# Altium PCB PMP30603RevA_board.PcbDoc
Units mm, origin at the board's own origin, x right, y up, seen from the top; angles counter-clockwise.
Board outline 38.1 x 27.94 mm, 2 copper layers (Top Layer, Bottom Layer), stack 1.575 mm thick; 29 components, 12 nets, 77 pads, 41 vias.
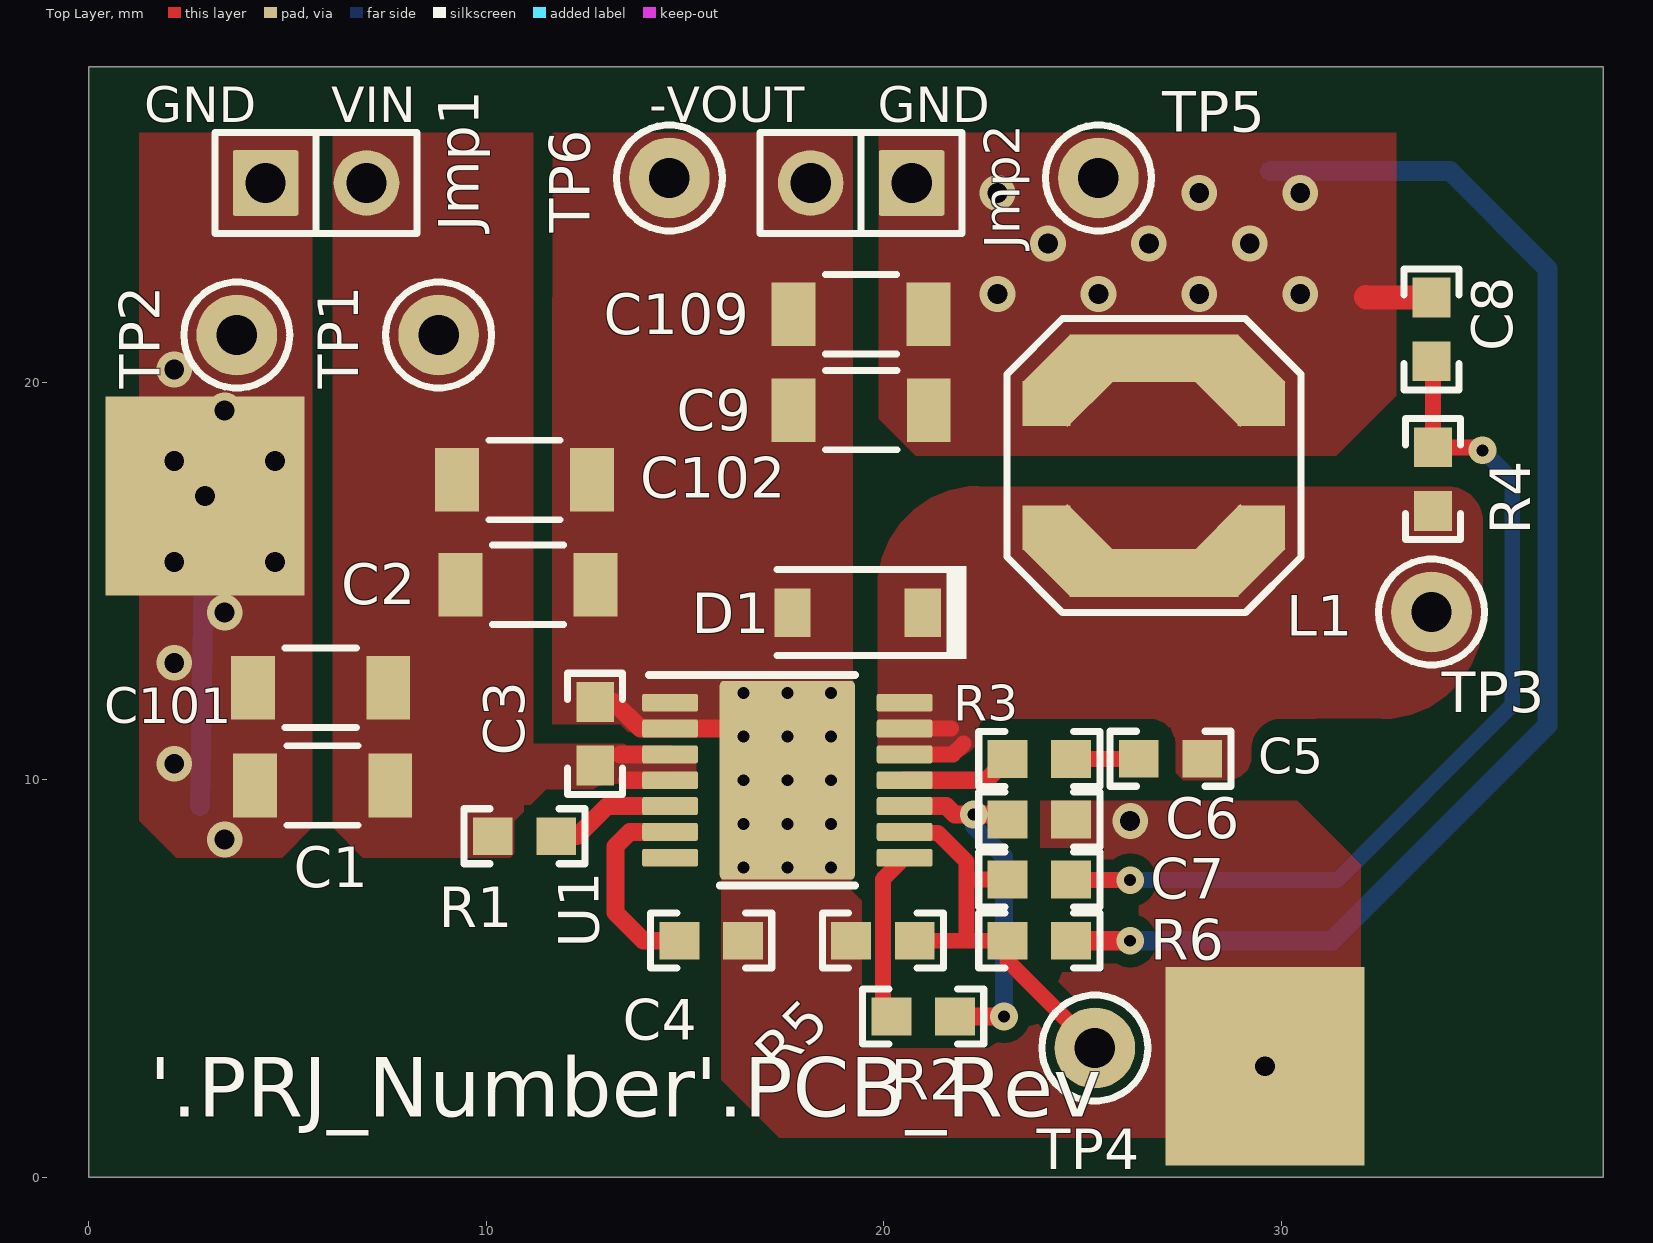
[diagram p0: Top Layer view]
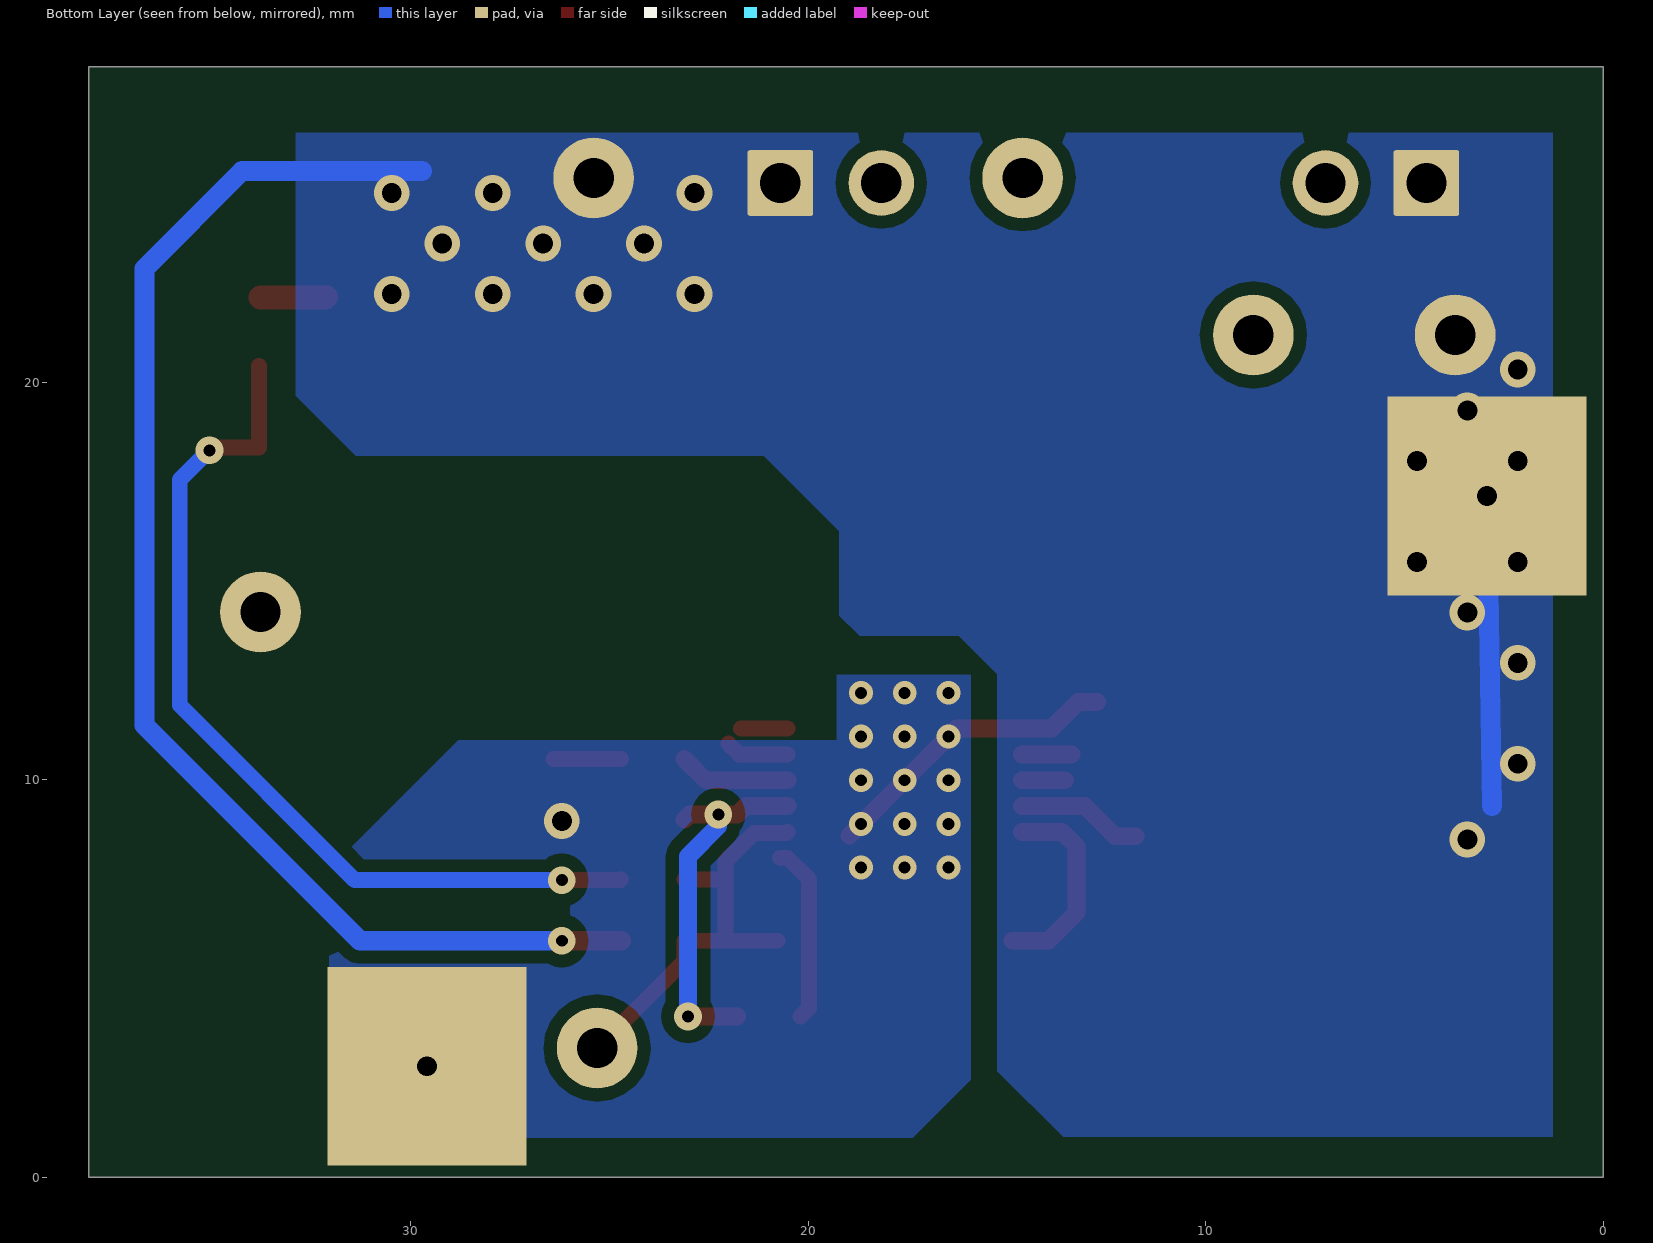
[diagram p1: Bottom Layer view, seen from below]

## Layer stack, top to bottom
Top Solder: solder mask 0.0102, Solder Resist, Dk 3.5
Top Layer: signal copper 0.0356
Dielectric1: core 1.5037, FR-4, Dk 4.8
Bottom Layer: signal copper 0.0356
Bottom Solder: solder mask 0.0102, Solder Resist, Dk 3.5

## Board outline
0,0 38.1,0 38.1,27.94 0,27.94

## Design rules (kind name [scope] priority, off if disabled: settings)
AcuteAngle [All] p1: minimum=4.50000000000000E+0001 checktracksonly=FALSE
AssemblyTestPointUsage [All] p1: valid=2
BoardOutlineClearance BoardOutlineClearance_MountingHoles [OnCopper and InComponentClass('Mounting Holes')] p1: gap=1 ignorepadtopadclearanceinfootprint=FALSE
BoardOutlineClearance BoardOutlineClearance_Poly [OnCopper and IsPoly] p2: gap=0.635 ignorepadtopadclearanceinfootprint=FALSE
BoardOutlineClearance [OnCopper and Not InComponentClass('Logo') and not InComponentClass('FiducialMark') and not InRegion(1000,500,4000,800) and not InPoly] p3: gap=1 ignorepadtopadclearanceinfootprint=FALSE
Clearance Clearance_Keepouts [((IsTrack Or IsArc) And Not InPoly) And IsFree and IsKeepOut vs ((IsTrack Or IsArc) And Not InPoly) And IsFree and IsKeepOut] p1: gap=0 ignorepadtopadclearanceinfootprint=FALSE
Clearance Clearance_Poly [InPolygon] p2: gap=0.32 ignorepadtopadclearanceinfootprint=TRUE
Clearance Clearance_FiducialMark [IsKeepOut and InComponentClass('FiducialMark') vs IsPad and InComponentClass('FiducialMark')] p3: gap=0 ignorepadtopadclearanceinfootprint=FALSE
Clearance [All] p4: gap=0.2 ignorepadtopadclearanceinfootprint=TRUE
ComponentClearance ComponentClearance_MountingHoles_FiducialMarks [InComponentClass('Mounting Holes') vs InComponentClass('FiducialMark')] p1: gap=1.27 collisioncheckmode=3 verticalgap=0.254 showdistances=FALSE
ComponentClearance ComponentClearance_Shunt [InComponentClass('Header') vs InComponentClass('Shunt')] p2: gap=0 collisioncheckmode=3 verticalgap=0 showdistances=FALSE
ComponentClearance ComponentClearance_Logo [InComponentClass('Logo')] p3: gap=1.27 collisioncheckmode=3 verticalgap=0.254 showdistances=FALSE
ComponentClearance ComponentClearance_ScrewToNut [(HasFootprint('NY PMS 440 0025 PH')) vs (HasFootprint('Keystone_1902C'))] p4: gap=0.127 collisioncheckmode=3 verticalgap=0.254 showdistances=FALSE
ComponentClearance ComponentClearance_MountingHoles [InComponentClass('Mounting Holes')] p5: gap=6.35 collisioncheckmode=3 verticalgap=2540 showdistances=FALSE
ComponentClearance ComponentClearance_SmallPassives [HasFootprint('0201*') or HasFootprint('0402*') or HasFootprint('0508') or HasFootprint('0603*') or HasFootprint('0612') or HasFootprint('0805*') or HasFootprint('0815*') or HasFootprint('0830*') or HasFootprint('1206*') or HasFootprint('1210*') or HasFootprint('1808*') or HasFootprint('1812*') or HasFootprint('1825*') or HasFootprint('2010*') or HasFootprint('2220*') or HasFootprint('2225*') or HasFootprint('2512*') or HasFootprint('2728*') or HasFootprint('3518*') vs HasFootprint('0201*') or HasFootprint('0402*') or HasFootprint('0508') or HasFootprint('0603*') or HasFootprint('0612') or HasFootprint('0805*') or HasFootprint('0815*') or HasFootprint('0830*') or HasFootprint('1206*') or HasFootprint('1210*') or HasFootprint('1808*') or HasFootprint('1812*') or HasFootprint('1825*') or HasFootprint('2010*') or HasFootprint('2220*') or HasFootprint('2225*') or HasFootprint('2512*') or HasFootprint('2728*') or HasFootprint('3518*')] p6: gap=0.38 collisioncheckmode=3 verticalgap=0.254 showdistances=FALSE
ComponentClearance ComponentClearance_THtoSMT [IsThruComponent vs IsSMTComponent] p7: gap=1.016 collisioncheckmode=3 verticalgap=0.762 showdistances=FALSE
ComponentClearance ComponentClearance_THtoTH [IsThruComponent vs IsThruComponent] p8: gap=0.762 collisioncheckmode=3 verticalgap=0.762 showdistances=FALSE
ComponentClearance [All] p9: gap=0.762 collisioncheckmode=3 verticalgap=0.254 showdistances=FALSE
DiffPairsRouting [All] p1: maxlimit=2.54 minlimit=0.254 mostfreqgap=0.254 toplayer_minwidth=0.381 toplayer_maxwidth=0.381 toplayer_prefwidth=0.381 bottomlayer_minwidth=0.381 bottomlayer_maxwidth=0.381 bottomlayer_prefwidth=0.381 maxuncoupledlength=25.4
FabricationTestPointUsage TestPointUsage [All] p1: valid=2 allowmultiple=FALSE
FabricationTestpoint Testpoint [All] p1: side=3 testpointundercomponent=TRUE minsize=1.016 maxsize=2.54 preferedsize=1.524 minholesize=0 maxholesize=1.016 preferedholesize=0.813 testpointgrid=0.025 allowsidetop=TRUE allowsidebottom=TRUE usegrid=TRUE gridtolerance=0
FanoutControl Fanout_LCC [IsLCC] p1: bgadir=Out bgaviamode=Centered fanoutstyle=Auto fanoutdirection=Alternating viagrid=0.025 // Fanout_LCC (Default Rule)
FanoutControl Fanout_BGA [IsBGA] p2: bgadir=Out bgaviamode=Centered fanoutstyle=Auto fanoutdirection=Alternating viagrid=0.025 // Fanout_BGA (Default Rule)
FanoutControl Fanout_Default [All] p4: bgadir=Out bgaviamode=Centered fanoutstyle=Auto fanoutdirection=Alternating viagrid=0.025 // Fanout_Default (Default Rule)
FanoutControl Fanout_Small [(CompPinCount < 5)] p5: bgadir=Out bgaviamode=Centered fanoutstyle=Auto fanoutdirection=OutThenIn viagrid=0.025 // Fanout_Small (Default Rule)
HoleSize [All] p1: absolutevalues=TRUE maxlimit=6.375 minlimit=0.3 maxpercent=80.000 minpercent=20.000
MinimumAnnularRing MinimumAnnularRing_ThermalPadVias [IsVia and InAnyComponent] p1: minimumring=0.15
MinimumAnnularRing [All] p2: minimumring=0.2
MinimumSolderMaskSliver MinimumSolderMaskSliver_Logo [InComponentClass('Logo') vs InComponentClass('Logo')] p1: minsoldermaskwidth=0.018
MinimumSolderMaskSliver [All] p2: minsoldermaskwidth=0.1
PlaneConnect [All] p1: planeconnectstyle=Relief reliefexpansion=0.254 reliefentries=4 reliefconductorwidth=0.254 reliefairgap=0.254
PolygonConnect [All] p1: connectstyle=Direct reliefconductorwidth=0.254 reliefentries=4 polygonreliefangle="90 Angle" airgapwidth=0.254
RoutingVias ThermalPadVias [IsVia and InAnyComponent] p1: holewidth=0.2 width=0.5 viastyle="Through Hole" minholewidth=0.2 minwidth=0.5 maxholewidth=0.33 maxwidth=0.6
RoutingVias [All] p2: holewidth=0.5 width=0.9 viastyle="Through Hole" minholewidth=0.3 minwidth=0.6 maxholewidth=1.016 maxwidth=1.651
SilkToBoardRegionClearance [Not ((IsComment or IsDesignator) And (Hide <> 'False')) and not InRegion(1000,500,4000,800)] p1:
SilkToSilkClearance SilkToSilkClearance_Pb-FreeLogo [(HasFootprint('Pb-Free_Overlay_Medium') OR HasFootprint('Pb-Free_Overlay_Small')) vs (HasFootprint('Pb-Free_Overlay_Medium') OR HasFootprint('Pb-Free_Overlay_Small'))] p1: silktosilkclearance=0
SilkToSilkClearance [All] p2: silktosilkclearance=0.1
SilkToSolderMaskClearance SilkToComponentPadClearance [(IsPad or IsFill or IsRegion) and InAnycomponent] p1: minsilkscreentomaskgap=0.127 clearancetoexposedcopper=TRUE
SilkToSolderMaskClearance "Silk to Solder Mask Opening" [All] p2: minsilkscreentomaskgap=0.1 clearancetoexposedcopper=FALSE
SolderMaskExpansion [All] p1: expansion=0.05
UnRoutedNet [All] p1: checkbadconnections=TRUE
Width [All] p1: maxlimit=2.54 minlimit=0.152 preferedwidth=0.254 checkconnectedcopper=TRUE
14 further rules are at their usual default settings.

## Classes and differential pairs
component class Header: Jmp1 Jmp2

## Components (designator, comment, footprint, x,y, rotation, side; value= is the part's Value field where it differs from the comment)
C1 "GCM31CR71A226KE02" 1206_180 5.88,9.858 r180 top value=22uF
C2 "GRM31CR72A225KA73L" 1206_190 11.049,14.913 r0 top value=2.2uF
C3 "GRM188R72A104KA35D" 0603 12.738,11.16 r90 top value=0.1uF
C4 "GRM188R71C223KA01D" 0603 15.659,5.953 r0 top value=0.022uF
C5 "GRM188R71C223KA01D" 0603 27.216,10.531 r0 top value=0.022uF
C6 "GRM188R71E105KA12D" 0603 23.914,9.001 r0 top value=1uF
C7 "GRM188R72A102KA01D" 0603 23.914,7.491 r180 top value=1000pF
C8 "GRM188R72A103KA01D" 0603 33.782,21.336 r270 top value=0.01uF
C9 "GRM31CR72A225KA73L" 1206_190 19.431,19.304 r180 top value=2.2uF
C101 "GCM31CR71A226KE02" 1206_180 5.83,12.319 r180 top value=OPEN
C102 "GRM31CR72A225KA73L" 1206_190 10.96,17.547 r0 top value=OPEN
C109 "GRM31CR72A225KA73L" 1206_190 19.427,21.717 r180 top value=OPEN
D1 "MBR0580-TP" SOD-123 19.342,14.209 r180 top value=80V
Jmp1 "TSW-102-07-G-S" TSW-102-07-G-S 5.715,25.019 r0 top
Jmp2 "TSW-102-07-G-S" TSW-102-07-G-S 19.431,25.019 r180 top
L1 "LPS6235-333MLB" LPS6235 26.797,17.907 r90 top value=33uH
R1 "CRCW0603681KFKEA" 0603 10.96,8.581 r0 top value=681k
R2 "CRCW06030000Z0EA" 0603 20.993,4.048 r0 top value=0
R3 "CRCW06033R32FKEA" 0603 23.914,10.525 r0 top value=3.32
R4 "CRCW060320K0FKEA" 0603 33.82,17.568 r90 top value=20.0k
R5 "CRCW060320K0FKEA" 0603 19.977,5.953 r0 top value=20.0k
R6 "CRCW0603576KFKEA" 0603 23.914,5.953 r0 top value=576k
TP1 "5000" Keystone5000 8.801,21.194 r90 top value=Red
TP2 "5001" Keystone5001 3.721,21.193 r90 top value=Black
TP3 "5002" Keystone5002 33.782,14.224 r90 top value=White
TP4 "5002" Keystone5002 25.311,3.253 r90 top value=White
TP5 "5001" Keystone5001 25.4,25.146 r90 top value=Black
TP6 "5117" Keystone5117 14.605,25.146 r90 top value=Blue
U1 "LM5161QPWPRQ1" PWP0014A_N 17.573,9.991 r0 top

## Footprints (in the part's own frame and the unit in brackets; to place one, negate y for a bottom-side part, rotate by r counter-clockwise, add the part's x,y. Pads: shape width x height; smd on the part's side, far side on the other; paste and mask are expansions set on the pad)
0603 [mm] "0603 from SM-752 data"
  rect 1x0.95 smd: 1(-0.8,0) 2(0.8,0)
  silkscreen extent -1.52,-0.69 1.52,0.69, body extent -0.87,-0.47 0.87,0.47, height 1
1206_180 [mm] "1206_180"
  rect 1.1x1.6 smd: 1(-1.7,0) 2(1.7,0)
  silkscreen extent -0.9,-1 0.9,1, body extent -1.75,-0.95 1.75,0.95, height 1.8
1206_190 [mm] "1206_190"
  rect 1.1x1.6 smd: 1(-1.7,0) 2(1.7,0)
  silkscreen extent -0.9,-1 0.9,1, body extent -1.75,-0.95 1.75,0.95, height 1.9
Keystone5000 [mil] "For Keystone 500x miniature loop terminals"
  round 80 hole 40: 1(0,0)
  silkscreen extent -52,-52 52,52, body extent -49,-49 49,49, height 182
Keystone5001 [mil] "For Keystone 500x miniature loop terminals"
  round 80 hole 40: 1(0,0)
  silkscreen extent -52,-52 52,52, body extent -49,-49 49,49, height 182
Keystone5002 [mil] "For Keystone 500x miniature loop terminals"
  round 80 hole 40: 1(0,0)
  silkscreen extent -52,-52 52,52, body extent -49,-49 49,49, height 182
Keystone5117 [mil] "For Keystone 500x miniature loop terminals"
  round 80 hole 40: 1(0,0)
  silkscreen extent -52,-52 52,52, body extent -49,-49 49,49, height 182
LPS6235 [mm] "Coilcraft recommended land pattern.  Document 587-2, rev 10/17/08"
  rect 1.2x4.25 smd: 1(-2.7,0) 2(2.7,0)
  rect 1.68x1.6 smd rot 135: 1(-2.126,-2.151) 2(2.126,2.151)
  rect 1.68x1.6 smd rot 45: 1(-2.126,2.151) 2(2.126,-2.151)
  rect 1.125x1.2 smd: 1(-1.562,2.7) 1(-1.562,-2.7) 2(1.562,2.7) 2(1.562,-2.7)
  silkscreen extent -3.7,-3.7 3.7,3.7, body extent -3.1,-3.1 3.1,3.1, height 3.52
PWP0014A_N [mm] "TSOP, 14-Leads, Body 5x4.4mm, Pitch 0.65mm, Thermal Pad 3x3.1 mm, IPC Medium Density"
  rrect22% 1.4x0.45 smd: 1(-2.95,1.95) 2(-2.95,1.3) 3(-2.95,0.65) 4(-2.95,0) 5(-2.95,-0.65) 6(-2.95,-1.3) 7(-2.95,-1.95) 8(2.95,-1.95) 9(2.95,-1.3) 10(2.95,-0.65) 11(2.95,0) 12(2.95,0.65) 13(2.95,1.3) 14(2.95,1.95)
  rrect6% 3.4x5 smd paste-2 mask-2: 15(0,0)
  rrect3% 3.155x3.255 on Top Paste: 15(0,0)
  rrect3% 3.155x3.255 on Top Solder: 15(0,0)
  silkscreen extent -3.47,-2.65 1.7,2.65, body extent -3.21,-2.5 3.21,2.5, height 1
SOD-123 [mm] "On Semi recommended land pattern"
  rect 0.915x1.22 smd: 1(-1.637,0) 2(1.637,0)
  silkscreen extent -2.74,-1.17 2.03,1.17, body extent -1.93,-0.9 1.93,0.9, height 1.35
TSW-102-07-G-S [mm] "Samtec 100mil, 1x2, 230 mil above insulator"
  rrect6% 1.65x1.65 hole 1.016: 1(-1.27,0)
  round 1.65 hole 1.016: 2(1.27,0)
  silkscreen extent -2.54,-1.27 2.54,1.27, body extent -2.54,-1.27 2.54,1.27, height 8.38

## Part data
C1: "CAP, CERM, 22 µF, 10 V,+/- 10%, X7R, AEC-Q200 Grade 1, 1206", Cap_Case=1206, Manufacturer=MuRata, TempCo=X7R, Tolerance_%=10, Value2=10V, ValueDisplayed=22µF
C2 C9: "CAP, CERM, 2.2 µF, 100 V,+/- 10%, X7R, 1206", Cap_Case=1206, Manufacturer=MuRata, Supplier Part Number 1=490-7209-1-ND, TempCo=X7R, Tolerance_%=10, Value2=100V, ValueDisplayed=2.2µF
C3: "CAP, CERM, 0.1 µF, 100 V,+/- 10%, X7R, 0603", Cap_Case=0603, Manufacturer=MuRata, Supplier Part Number 1=490-3285-1-ND, TempCo=X7R, Tolerance_%=10, Value1=Unknown, Value2=100V, ValueDisplayed=0.1µF
C4 C5: "CAP, CERM, 0.022 µF, 16 V,+/- 10%, X7R, 0603", Cap_Case=0603, Manufacturer=MuRata, Supplier Part Number 1=490-1527-1-ND, TempCo=X7R, Tolerance_%=10, Value2=16V, ValueDisplayed=0.022µF
C6: "CAP, CERM, 1 µF, 25 V,+/- 10%, X7R, 0603", Cap_Case=0603, Manufacturer=MuRata, Supplier Part Number 1=490-5307-1-ND, TempCo=X7R, Tolerance_%=10, Value2=25V, ValueDisplayed=1µF
C7: "CAP, CERM, 1000 pF, 100 V,+/- 10%, X7R, 0603", Cap_Case=0603, Manufacturer=MuRata, Supplier Part Number 1=490-1472-1-ND, TempCo=X7R, Tolerance_%=10, Value2=100V, ValueDisplayed=1000pF
C8: "CAP, CERM, 0.01 µF, 100 V,+/- 10%, X7R, 0603", Cap_Case=0603, Manufacturer=MuRata, Supplier Part Number 1=GRM188R72A103KA01D-ND, TempCo=X7R, Tolerance_%=10, Value2=100V, ValueDisplayed=0.01µF
C101: "CAP, CERM, 22 µF, 10 V,+/- 10%, X7R, AEC-Q200 Grade 1, 1206", Cap_Case=1206, Manufacturer=MuRata, TempCo=X7R, Tolerance_%=10, Value2=10V, ValueDisplayed=OPEN
C102 C109: "CAP, CERM, 2.2 µF, 100 V,+/- 10%, X7R, 1206", Cap_Case=1206, Manufacturer=MuRata, Supplier Part Number 1=490-7209-1-ND, TempCo=X7R, Tolerance_%=10, Value2=100V, ValueDisplayed=OPEN
D1: "Diode, Schottky, 80 V, 0.5 A, SOD-123", Manufacturer="Micro Commercial Components", Supplier Part Number 1=MBR0580-TPMSCT-ND, Value1=0.5A, Value2=0.8V
Jmp1 Jmp2: "Header, 100mil, 2x1, Gold, TH", Manufacturer=Samtec, Supplier Part Number 1=SAM1029-02-ND
L1: "Inductor, Shielded Drum Core, Ferrite, 33 µH, 1.3 A, 0.18 ohm, SMD", Manufacturer=Coilcraft, Value1="0.18 ohm", Value2=1.3A, ValueDisplayed=33µH
R1: "RES, 681 k, 1%, 0.1 W, 0603", Manufacturer=Vishay-Dale, Power_W=0.1, Supplier Part Number 1=541-681KHCT-ND, TempCo="100 ppm/C", Tolerance_%=1, Value1=1%, Value2=0.1W, Value_Code=681k
R2: "RES, 0, 5%, 0.1 W, 0603", Manufacturer=Vishay-Dale, Power_W=0.1, Supplier Part Number 1=541-0.0GCT-ND, TempCo="200 ppm/C", Tolerance_%=5, Value1=5%, Value2=0.1W, Value_Code=0000, ValueDisplayed=0
R3: "RES, 3.32, 1%, 0.1 W, 0603", Manufacturer=Vishay-Dale, Power_W=0.1, Supplier Part Number 1=541-3.32HHCT-ND, TempCo="100 ppm/C", Tolerance_%=1, Value1=1%, Value2=0.1W, Value_Code=3R32, ValueDisplayed=3.32
R4 R5: "RES, 20.0 k, 1%, 0.1 W, 0603", Manufacturer=Vishay-Dale, Power_W=0.1, Supplier Part Number 1=541-20.0KHCT-ND, TempCo="100 ppm/C", Tolerance_%=1, Value1=1%, Value2=0.1W, Value_Code=20k0, ValueDisplayed=20.0k
R6: "RES, 576 k, 1%, 0.1 W, 0603", Manufacturer=Vishay-Dale, Power_W=0.1, Supplier Part Number 1=541-576KHCT-ND, TempCo="100 ppm/C", Tolerance_%=1, Value1=1%, Value2=0.1W, Value_Code=576k
TP1: "Test Point, Miniature, Red, TH", Manufacturer=Keystone, Supplier Part Number 1=5000K-ND
TP2 TP5: "Test Point, Miniature, Black, TH", Manufacturer=Keystone, Supplier Part Number 1=5001K-ND
TP3 TP4: "Test Point, Miniature, White, TH", Manufacturer=Keystone, Supplier Part Number 1=5002K-ND
TP6: "Test Point, Miniature, Blue, TH", Color=Blue, Manufacturer=Keystone, Supplier Part Number 1=36-5117-ND
U1: "Wide Input 4.5-V to 100-V, 1-A Synchronous Buck / Fly-Buck Converter, PWP0014A (TSSOP-14)", Alternate Manufacturer="Texas Instruments", Alternate PartNumber=LM5161QPWPTQ1

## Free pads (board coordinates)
  rect 5x5 hole 0.5: 1(29.591,2.794) 2(2.921,17.145)

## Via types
v1: diameter 0.9, hole 0.5, Top Layer to Bottom Layer, 20 vias
v2: diameter 0.6, hole 0.3, Top Layer to Bottom Layer, 9 vias
v3: diameter 0.6, hole 0.3, Top Layer to Bottom Layer, tented both sides, 6 vias
v4: diameter 0.7, hole 0.3, Top Layer to Bottom Layer, tented top, 3 vias
v5: diameter 0.7, hole 0.3, Top Layer to Bottom Layer, 2 vias
v6: diameter 0.9, hole 0.5, Top Layer to Bottom Layer, tented top, 1 vias

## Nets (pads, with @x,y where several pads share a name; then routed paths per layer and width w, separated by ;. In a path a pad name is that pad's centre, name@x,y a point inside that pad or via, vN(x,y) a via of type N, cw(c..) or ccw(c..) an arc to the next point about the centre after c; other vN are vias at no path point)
GND: C1.2 C8.1 C9.1 C101.2 C109.1 Jmp1.1 Jmp2.1 L1.2 pad.2 R6.2 TP2.1 TP5.1 | length 43.2
  Top Layer w0.5: R6.2 v4(26.2,5.953)
  Top Layer w0.6: 32.131,22.147 32.142,22.136 C8.1
  Bottom Layer w0.5: 2.794,9.341 pad.2 ; v4(26.2,5.953) 31.28,5.953 36.703,11.376 36.703,22.86 34.245,25.318 29.718,25.318
  other v1: 3.416,8.5 2.146,10.405 2.146,12.945 3.416,14.215 2.146,15.485 4.686,15.485 2.146,18.025 4.686,18.025 3.416,19.295 2.146,20.327 22.86,22.225 25.4,22.225 27.94,22.225 30.48,22.225 24.13,23.495 26.67,23.495 29.21,23.495 27.94,24.765 30.48,24.765
  other v6: 22.86,24.765
NetC1_1: C1.1 C2.1 C3.1 C101.1 C102.1 Jmp1.2 R1.1 TP1.1 U1.3 U1.4 | length 2.3
  Top Layer w0.45: 13.373,10.641 U1.3 ; 13.542,9.991 U1.4
NetC2_2: C2.2 C3.2 C4.2 C6.2 C9.2 C102.2 C109.2 D1.2 Jmp2.2 pad.1 R5.1 TP6.1 U1.1 U1.2 U1.15@17.573,9.991 | length 9.5
  Top Layer w0.45: C3.2 13.208,11.96 13.877,11.291 U1.2 16.273,11.291 v2(16.473,11.091) v2(17.573,9.991) v2(18.673,8.891) U1.15@18.961,8.603 ; pad.1@27.669,2.794 pad.1
  other v1: 26.2,8.964
  other v2: 16.473,8.891 17.573,8.891 16.473,9.991 18.673,9.991 17.573,11.091 18.673,11.091
  other v3: 16.473,7.791 17.573,7.791 18.673,7.791 16.473,12.191 17.573,12.191 18.673,12.191
NetC4_1: C4.1 U1.6 | length 5.1
  Top Layer w0.45: U1.6 13.61,8.691 13.246,8.327 13.246,6.66 13.953,5.953 C4.1
NetC5_1: C5.1 R3.2 | length 1.7
  Top Layer w0.4: R3.2 26.41,10.525 C5.1
NetC5_2: C5.2 D1.1 L1.1 R4.1 TP3.1 U1.12 U1.13 U1.14 | length 2.8
  Top Layer w0.4: U1.12 21.739,10.641 22.009,10.911 ; U1.13 21.695,11.291
NetC6_1: C6.1 R2.2 U1.10 | length 9.4
  Top Layer w0.45: U1.10 21.572,9.341 21.785,9.128 v4(22.263,9.128) 22.987,9.128 C6.1 ; R2.2 v5(23.025,4.048)
  Bottom Layer w0.45: v4(22.263,9.128) 22.263,8.836 23.025,8.074 v5(23.025,4.048)
NetC7_1: C7.1 C8.2 R4.2 | length 22.9
  Top Layer w0.4: C7.1 24.728,7.477 v4(26.2,7.477) ; C8.2@33.82,20.413 R4.2 v5@34.993,18.368
  Bottom Layer w0.4: v4(26.2,7.477) 31.406,7.477 35.814,11.885 35.814,17.547 v5(35.069,18.292)
NetC7_2: C7.2 R5.2 R6.1 TP4.1 U1.9 | length 10.9
  Top Layer w0.4: U1.9 20.548,8.666 21.36,8.666 22.085,7.941 22.085,7.477 ; R5.2 22.009,5.953 ; C7.2 22.1,7.491 22.085,7.477 ; TP4.1 23.114,5.45 R6.1 22.009,5.953 ; 22.009,5.953 22.085,6.029 22.085,7.477
NetR1_2: R1.2 U1.5 | length 3.2
  Top Layer w0.45: R1.2 12.285,8.581 13.045,9.341 U1.5
NetR2_1: R2.1 U1.8 | length 4.5
  Top Layer w0.4: R2.1 19.977,4.264 19.977,7.495 U1.8 U1.8@20.714,8.041
NetR3_1: R3.1 U1.11 | length 2.8
  Top Layer w0.45: U1.11 22.58,9.991 R3.1
pads on no net: U1.7 U1.15@17.573,9.991

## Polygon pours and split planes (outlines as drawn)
GND on Top Layer "TOP_LAYER_GND_P050" (solid, remove dead copper, pour order 50): 20.803,18.161 31.386,18.161 32.893,19.668 32.893,26.289 19.875,26.289 19.875,19.089
no net on Top Layer "TOP_LAYER_NONET_P048" (solid, remove dead copper, pour order 48): 29.502,12.117
NetC5_2 on Top Layer "TOP_LAYER_NETC5_2_P044" (solid, remove dead copper, pour order 44): 30.226,17.379 34.2,17.379 cw(c34.2,16.51) 35.069,16.51 35.069,14.084 cw(c32.529,14.084) 32.529,11.544 31.024,11.554 cw(c30.772,13.954) 30.772,11.541 30.01,11.541 ccw(c30.01,10.779) 29.248,10.779 29.248,10.61 cw(c28.629,10.61) 28.629,9.991 27.535,9.991 cw(c27.535,10.183) 27.343,10.183 27.343,10.911 ccw(c26.714,10.911) 26.714,11.541 22.655,11.541 ccw(c22.655,11.25) 22.364,11.25 22.364,11.052 cw(c22.019,11.051) 22.263,10.808 cw(c21.331,11.739) 21.331,10.422 19.977,10.422 cw(c19.977,10.549) 19.85,10.549 19.85,14.843 cw(c22.39,14.843) 22.39,17.383
NetC2_2 on Top Layer "TOP_LAYER_NETC2_2_P038" (solid, remove dead copper, pour order 38): 15.913,10.736 15.913,2.46 17.373,1 28.232,1 32.004,4.772 32.004,7.876 30.404,9.476 23.025,9.476 19.977,6.428 19.184,7.221 19.184,10.744
NetC2_2 on Top Layer "TOP_LAYER_NETC2_2_P036" (solid, remove dead copper, pour order 36): 15.209,11.072 13.702,11.072 13.373,11.401 11.656,11.401 11.656,18.018 11.674,26.289 19.215,26.289 19.215,11.16
GND on Top Layer "TOP_LAYER_GND_P034" (solid, remove dead copper, pour order 34): 5.626,26.289 5.626,8.803 4.864,8.041 2.195,8.041 1.27,8.966 1.27,26.289
NetC1_1 on Top Layer "TOP_LAYER_NETC1_1_P032" (solid, remove dead copper, pour order 32): 15.278,10.906 11.176,10.906 11.176,26.289 6.134,26.289 6.134,8.803 6.896,8.041 10.596,8.041 10.706,8.151 10.706,8.964 11.505,9.763 15.278,9.763
no net on Top Layer "TOP_LAYER_NONET_P016" (solid, remove dead copper, pour order 16): 19.773,10.362
GND on Bottom Layer "BOTTOM_LAYER_GND_P052" (solid, remove dead copper, pour order 52): 1.27,1.016 13.589,1.016 15.24,2.667 15.24,12.653 16.209,13.622 18.707,13.622 19.215,14.13 19.215,16.258 21.118,18.161 31.386,18.161 32.893,19.668 32.893,26.289 1.27,26.289
NetC2_2 on Bottom Layer "BOTTOM_LAYER_NETC2_2_P040" (solid, remove dead copper, pour order 40): 19.277,10.999 19.277,12.641 15.913,12.641 15.913,2.46 17.373,1 28.232,1 32.058,4.826 32.058,7.747 28.806,10.999

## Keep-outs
Keep-Out Layer:
  text ".Layer_Name" at 14.656,-21.806 h1.52

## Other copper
Top Layer:
  pour cut-out: 19.184,9.231 19.184,7.618 19.311,7.491 19.573,7.491 19.773,7.691 19.773,9.231
  text ".Layer_Name" at 14.656,-21.806 h1.52
Bottom Layer:
  text ".Layer_Name" at 14.656,-21.806 h1.52

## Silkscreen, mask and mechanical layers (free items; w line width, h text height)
Top Overlay:
  text "GND" at 1.397,26.543 h0.9
  text "VIN" at 6.096,26.543 h0.9
  text "-VOUT" at 14.097,26.543 h0.9
  text "GND" at 19.85,26.543 h0.9
  text "'.PRJ_Number'.PCB_Rev" at 1.524,1.524 h1.5
  text ".Layer_Name" at 14.656,-21.806 h1.52
Bottom Overlay:
  text ".Layer_Name" at 14.656,-21.806 h1.52
Top Paste:
  text ".Layer_Name" at 14.656,-21.806 h1.52
Bottom Paste:
  text ".Layer_Name" at 14.656,-21.806 h1.52
Top Solder:
  text ".Layer_Name" at 14.656,-21.806 h1.52
  text ".Layer_Name" at 14.656,-21.806 h1.52
Bottom Solder:
  text ".Layer_Name" at 14.656,-21.806 h1.52
Drill Guide:
  text ".Layer_Name" at 14.656,-21.806 h1.52
M1 Board Outline:
  the board outline again, w0.254
  text ".Layer_Name" at 14.656,-21.806 h1.52
M2 Board Dimensions:
  rectangle: 0,-6.985 3.175,-3.81
  rectangle: 3.175,-10.16 12.7,-6.985
  lines w0.178: 0,-6.985 25.4,-6.985 ; 3.175,-10.16 3.175,-3.81 ; 6.35,-10.16 6.35,-3.81 ; 12.7,-10.16 12.7,-3.81 ; 19.05,-10.16 19.05,-3.81 ; 0,-10.16 25.4,-10.16 25.4,-3.81 0,-3.81 0,-10.16
  text "'.Print_Date' '.Print_Time'" at 0,29.21 h1.85
  text ".Layer_Name" at 14.656,-21.806 h1.52
M3 3D STEP Top:
  text ".Layer_Name" at 14.656,-21.806 h1.52
M4 3D STEP Bottom:
  text ".Layer_Name" at 14.656,-21.806 h1.52
M5 Assembly Top:
  lines w0.254: -7.417,-23.626 160.223,-23.626 ; -7.417,-18.462 160.274,-18.462 ; -7.417,-13.297 -7.417,-28.791 94.31,-28.791 160.274,-28.791 160.274,-13.297 -7.404,-13.297 -7.404,-28.791 32.614,-28.791 ; 55.194,-28.791 55.194,-13.297 ; 87.376,-18.462 87.376,-13.297 ; 108.712,-18.462 108.712,-13.297 ; 124.511,-28.956 124.511,-23.804
  text "COMPONENTS MARKED 'DNP' SHOULD NOT BE POPULATED." at 29.299,-8.09 h1.52
  text "ASSEMBLY VARIANT:" at 29.286,-11.024 h1.52
  text ".VariantName" at 55.601,-11.024 h1.52
  text "PCB VIEWED FROM TOP SIDE" at -5.804,-16.654 h1.52
  text "BOARD #:" at 57.099,-16.654 h1.52
  text ".PRJ_Number" at 70.955,-16.654 h1.52
  text "REV:" at 92.405,-16.654 h1.52
  text ".PCB_Rev" at 99.809,-16.654 h1.52
  text "SVN REV:" at 113.69,-16.654 h1.52
  text ".VersionControl_RevNumber" at 126.543,-16.654 h1.52
  text "TID #:" at 57.099,-21.819 h1.52
  text ".TID" at 70.955,-21.819 h1.52
  text "PLOT NAME =" at -5.804,-27.034 h1.52
  text ".plot_File_Name" at 14.656,-27.034 h1.52
  text "GENERATED    :" at 57.15,-27.034 h1.52
  text ".Print_Date" at 79.235,-27.034 h1.52
  text ".Print_Time" at 97.752,-27.034 h1.52
  text "TEXAS INSTRUMENTS" at 129.87,-27.034 h1.52
M6 Assembly Bottom:
  lines w0.254: -7.429,-18.474 160.261,-18.474 ; -7.379,-23.639 160.261,-23.639 ; 28.334,-28.969 28.334,-23.817 ; 44.133,-18.474 44.133,-13.31 ; 65.468,-18.474 65.468,-13.31 ; 97.65,-28.804 97.65,-13.31 ; 120.231,-28.804 160.249,-28.804 160.249,-13.31 -7.429,-13.31 -7.429,-28.804 58.534,-28.804 160.261,-28.804 160.261,-13.31
  text "COMPONENTS MARKED 'DNP' SHOULD NOT BE POPULATED." at 154.991,-8.077 h1.52
  text ".VariantName" at 128.473,-11.024 h1.52
  text "ASSEMBLY VARIANT:" at 154.864,-11.024 h1.52
  text ".VersionControl_RevNumber" at 26.302,-16.667 h1.52
  text "SVN REV:" at 39.154,-16.667 h1.52
  text ".PCB_Rev" at 53.035,-16.667 h1.52
  text "REV:" at 60.439,-16.667 h1.52
  text ".PRJ_Number" at 81.89,-16.667 h1.52
  text "BOARD #:" at 95.745,-16.667 h1.52
  text "PCB VIEWED FROM BOTTOM SIDE" at 158.648,-16.667 h1.52
  text ".TID" at 81.89,-21.831 h1.52
  text "TID #:" at 95.745,-21.831 h1.52
  text "TEXAS INSTRUMENTS" at 22.974,-27.047 h1.52
  text ".Print_Time" at 55.093,-27.047 h1.52
  text ".Print_Date" at 73.609,-27.047 h1.52
  text "GENERATED    :" at 95.694,-27.047 h1.52
  text ".plot_File_Name" at 138.189,-27.047 h1.52
  text "PLOT NAME =" at 158.648,-27.047 h1.52
M9 Title Sheet:
  drawing of 57 lines, arcs and shapes, not listed
  text "1" at 18.792,204.127 h1.78
  text "2" at 82.182,204.127 h1.78
  text "3" at 145.411,204.127 h1.78
  text "4" at 209.08,204.127 h1.78
  text "5" at 272.555,204.127 h1.78
  text "6" at 336.182,204.127 h1.78
  text "A" at -10.579,175.095 h1.78
  text "A" at 365.341,175.095 h1.78
  text "B" at -10.579,114.643 h1.78
  text "B" at 365.341,114.643 h1.78
  text "C" at -10.579,54.318 h1.78
  text "C" at 365.341,54.318 h1.78
  text "PROJECT TITLE:" at 288.125,7.048 h1.14
  text ".PRJ_Title" at 289.395,3.662 h1.78
  text "DESIGNED FOR:" at 288.125,-0.597 h1.14
  text ".PRJ_Customer" at 289.395,-4.153 h1.78
  text "D" at -10.579,-5.88 h1.78
  text "D" at 365.341,-5.88 h1.78
  text "FILE NAME:" at 288.125,-8.217 h1.14
  text ".PCB_File_Name_No_Path" at 289.395,-11.265 h1.78
  text "Texas Instruments (TI) and/or its licensors do not warrant the accuracy or completeness of this specification" at 161.9,-15.376 h1.14
  text "ENGINEER:" at 288.125,-15.583 h1.14
  text "LAYOUT BY:" at 326.352,-15.583 h1.14
  text "or any information contained therein. TI and/or its licensors do not warrant that this design will meet" at 160.757,-18.237 h1.14
  text ".PRJ_Engineer" at 289.395,-19.52 h1.78
  text ".PCB_Layout" at 327.635,-19.52 h1.78
  text "the specifications, will be suitable for your application or fit for any particular purpose, or will operate in" at 160.757,-21.099 h1.14
  text ".Layer_Name" at 14.656,-21.806 h1.52
  text "ALTIUM DESIGNER VERSION:" at 326.352,-23.457 h1.14
  text "an implementation. TI and/or its licensors do not warrant that the design is production worthy. You should" at 160.757,-23.961 h1.14
  text "completely validate and test your design implementation to confirm the system functionality for your application." at 161.9,-26.822 h1.14
  text ".print_Scale" at 289.395,-26.843 h1.78
  text ".Application_BuildNumber" at 327.635,-26.843 h1.78
  text "1" at 18.792,-32.093 h1.78
  text "2" at 82.182,-32.093 h1.78
  text "3" at 145.411,-32.093 h1.78
  text "4" at 209.08,-32.093 h1.78
  text "5" at 272.555,-32.093 h1.78
  text "6" at 336.182,-32.093 h1.78
M10 Fab Notes:
  drawing of 189 lines, arcs and shapes, not listed
  text "DESIGN INFORMATION" at 314.503,161.447 h1.52
  text "MIN. TRACK WIDTH:" at 298.131,158.091 h1.52
  text "8" at 325.976,158.091 h1.52
  text "MIL" at 329.907,158.091 h1.52
  text "MIN. CLEARANCE:" at 298.131,154.938 h1.52
  text "0.2" at 324.452,154.938 h1.52
  text "mm" at 329.907,154.938 h1.52
  text "MIN. VIA PAD SIZE:" at 298.131,151.785 h1.52
  text "24" at 325.214,151.785 h1.52
  text "MIL" at 329.907,151.785 h1.52
  text "0.05mm (2MIL)" at 315.784,148.486 h1.52
  text "MINIMUM ANNULAR RING" at 289.769,148.277 h1.52
  text "EXTERNAL" at 333.768,148.277 h1.52
  text "PER" at 294.849,145.48 h1.52
  text "IPC-D-275 CLASS 2 LEVEL C" at 300.437,145.48 h1.52
  text "MIL, HOLES" at 338.238,142.928 h1.52
  text "+/-" at 328.27,142.709 h1.52
  text "+/-" at 349.961,142.709 h1.52
  text "REGISTRATION TOLERANCES:" at 289.769,142.682 h1.52
  text "METAL" at 320.243,142.682 h1.52
  text "5" at 334.879,142.683 h1.52
  text "3" at 356.037,142.683 h1.52
  text "MIL" at 358.99,142.682 h1.52
  text "HOLE SIZE TOLERANCE (UNLESS OTHERWISE SPECIFIED):" at 289.769,140.185 h1.52
  text "+/-" at 349.961,140.112 h1.52
  text "3" at 356.037,140.085 h1.52
  text "MIL" at 358.99,140.085 h1.52
  text "MATERIAL:" at 287.87,136.589 h1.52
  text "FR-4 High Tg" at 312.926,133.324 h1.52
  text "X" at 309.257,133.122 h1.52
  text "FR-408" at 298.563,133.007 h1.52
  text "OTHER" at 336.358,133.007 h1.52
  text "62 MIL (1.6mm) +/-10%" at 306.694,129.374 h1.52
  text "X" at 303.643,129.312 h1.52
  text "THICKNESS:" at 289.769,129.165 h1.52
  text "OTHER" at 339.33,129.165 h1.52
  text "TOLERANCE:" at 289.769,125.652 h1.52
  text "X" at 311.314,125.652 h1.52
  text "ANSI IPC-6012 TYPE 3 CLASS 2" at 315.836,125.652 h1.52
  text "OTHER +/-" at 315.835,121.989 h1.52
  text "BOW & TWIST:" at 289.769,118.302 h1.52
  text "X" at 311.314,118.302 h1.52
  text "ANSI IPC-6012 TYPE 3 CLASS 2" at 315.836,118.302 h1.52
  text "OTHER +/-" at 315.835,114.576 h1.52
  text "DRILLING:" at 287.87,111.258 h1.52
  text "NC_DRILL FILES" at 332.599,108.586 h1.52
  text "REFERENCE:" at 289.769,108.486 h1.52
  text "X" at 306.463,108.484 h1.52
  text "AS SHOWN" at 310.984,108.486 h1.52
  text "X" at 329.348,108.486 h1.52
  text "OTHER" at 340.168,104.873 h1.52
  text "PTH COPPER THICKNESS:" at 289.761,104.783 h1.52
  text "X" at 318.697,104.783 h1.52
  text "20-30 um" at 321.948,104.783 h1.52
  text "BOARD FINISH:" at 287.87,101.034 h1.52
  text "SILKSCREEN:" at 291.812,98.237 h1.52
  text "X" at 316.14,98.237 h1.52
  text "TOP" at 319.112,98.237 h1.52
  text "X" at 329.094,98.237 h1.52
  text "BOTTOM" at 332.091,98.237 h1.52
  text "SILKSCREEN COLOR:" at 291.812,94.295 h1.52
  text "X" at 316.115,94.295 h1.52
  text "WHITE" at 319.112,94.295 h1.52
  text "OTHER" at 332.091,94.295 h1.52
  text "X" at 319.442,90.652 h1.52
  text "GREEN" at 322.439,90.652 h1.52
  text "OTHER" at 338.136,90.652 h1.52
  text "SOLDER RESIST COLOR:" at 291.812,90.477 h1.52
  text "X" at 319.442,86.734 h1.52
  text "MATTE" at 322.439,86.734 h1.52
  text "SEMI-GLOSS" at 338.125,86.717 h1.52
  text "IMMERSION GOLD (ENIG)" at 314.819,82.345 h1.52
  text "ENEPIG" at 348.793,82.162 h1.52
  text "SURFACE FINISH:" at 287.87,82.136 h1.52
  text "X" at 310.298,82.136 h1.52
  text "IMM. TIN/SILVER OR EQUIV" at 296.24,78.649 h1.52
  text "OTHER" at 332.599,78.549 h1.52
  text "ARRAY/PANEL:" at 287.87,74.602 h1.52
  text "CUT AND TRIM PER M1 BOARD OUTLINE" at 314.819,74.393 h1.52
  text "N.C. ROUTE" at 314.819,70.94 h1.52
  text "X" at 332.295,70.94 h1.52
  text "V. SCORE" at 336.816,70.94 h1.52
  text "CERTIFICATION:" at 287.87,67.66 h1.52
  text "MATERIALS AND WORKMANSHIP FOR ALL PCBS" at 306.285,67.66 h1.52
  text "TO MEET OR EXCEED THE REQUIREMENTS OF:" at 306.285,65.271 h1.52
  text "X" at 297.078,62.003 h1.52
  text "ANSI IPC-A-600F CLASS ->" at 300.329,62.003 h1.52
  text "X" at 342.188,62.003 h1.52
  text "2" at 344.982,62.003 h1.52
  text "1" at 336.981,61.965 h1.52
  text "3" at 353.973,61.965 h1.52
  text "X" at 317.702,58.252 h1.52
  text "RoHS" at 320.953,58.252 h1.52
  text "OTHER" at 337.321,58.252 h1.52
  text "PER ORDER" at 347.407,58.252 h1.52
  text "ALL BOARDS MUST MEET OR EXCEED UL94-V0 REQUIREMENTS." at 288.569,54.345 h1.52
  text "PCB MUST BEAR THE UL94V-0 UL REGISTERED MATERIAL ID NUMBER" at 288.569,51.397 h1.52
  text "ADDITIONAL REQUIREMENTS:" at 287.87,47.094 h1.52
  text "MICROSECTION:" at 289.769,44.373 h1.52
  text "YES" at 312.775,44.373 h1.52
  text "REQUIRED" at 334.657,40.707 h1.52
  text "BARE BOARD ELEC. TEST:" at 289.769,40.634 h1.52
  text "NONE" at 322.935,40.634 h1.52
  text "X" at 331.66,40.634 h1.52
  text "PER ORDER" at 349.693,40.634 h1.52
  text "XX MIL VIAS REQUIRE NON-CONDUCTIVE FILL AND PLANARIZE" at 294.04,35.428 h1.5
  text "XX MIL VIAS REQUIRE CONDUCTIVE FILL AND PLANARIZE" at 294.243,32.787 h1.52
  text "OUTER XX MIL TRACES REQUIRE 50 OHM SINGLE-ENDED IMPEDANCE" at 294.218,28.637 h1.47
  text "LAYER 2 & 3 (INNER LAYERS) XX MIL WIDE, XX MIL SPACE / TRACES REQUIRE 100 OHM DIFFERENTIAL IMPEDANCE" at 294.015,22.65 h1.52
  text ".Layer_Name" at 14.656,-21.806 h1.52
M11 Gerber Information:
  lines w0.254: -7.417,-23.626 160.223,-23.626 ; -7.417,-18.462 160.274,-18.462 ; -7.417,-13.297 -7.417,-28.791 94.31,-28.791 160.274,-28.791 160.274,-13.297 -7.404,-13.297 -7.404,-28.791 32.614,-28.791 ; 55.194,-28.791 55.194,-13.297 ; 87.376,-18.462 87.376,-13.297 ; 108.712,-18.462 108.712,-13.297 ; 124.511,-28.956 124.511,-23.804
  text "ALL ARTWORK VIEWED FROM TOP SIDE" at -5.804,-16.654 h1.52
  text "BOARD #:" at 57.099,-16.654 h1.52
  text ".PRJ_Number" at 70.955,-16.654 h1.52
  text "REV:" at 92.405,-16.654 h1.52
  text ".PCB_Rev" at 99.809,-16.654 h1.52
  text "SVN REV:" at 113.69,-16.654 h1.52
  text ".VersionControl_RevNumber" at 126.543,-16.654 h1.52
  text "LAYER NAME =" at -5.804,-21.806 h1.52
  text "TID #:" at 57.099,-21.819 h1.52
  text ".TID" at 70.955,-21.819 h1.52
  text "PLOT NAME =" at -5.804,-27.034 h1.52
  text ".plot_File_Name" at 14.656,-27.034 h1.52
  text "GENERATED    :" at 57.15,-27.034 h1.52
  text ".Print_Date" at 79.235,-27.034 h1.52
  text ".Print_Time" at 97.752,-27.034 h1.52
  text "TEXAS INSTRUMENTS" at 129.87,-27.034 h1.52
M12 Stackup:
  drawing of 191 lines, arcs and shapes, not listed
  text "Layer" at 248.865,192.024 h1.52
  text "Name" at 259.277,192.024 h1.52
  text "Material" at 282.892,192.024 h1.52
  text "Thickness" at 304.731,192.024 h1.52
  text "Constant" at 321.236,192.024 h1.52
  text "Board Layer Stack" at 335.711,192.024 h1.52
  text "1" at 248.865,188.976 h1.52
  text "Top Overlay" at 259.277,188.976 h1.52
  text "2" at 248.865,185.928 h1.52
  text "Top Solder" at 259.277,185.928 h1.52
  text "Solder Resist" at 282.892,185.928 h1.52
  text "0.40mil" at 304.731,185.928 h1.52
  text "3.5" at 321.236,185.928 h1.52
  text "3" at 248.865,182.88 h1.52
  text "Top Layer" at 259.277,182.88 h1.52
  text "Copper" at 282.892,182.88 h1.52
  text "1.40mil" at 304.731,182.88 h1.52
  text "4" at 248.865,179.832 h1.52
  text "Dielectric1" at 259.277,179.832 h1.52
  text "FR-4" at 282.892,179.832 h1.52
  text "59.20mil" at 304.731,179.832 h1.52
  text "4.8" at 321.236,179.832 h1.52
  text "5" at 248.865,176.784 h1.52
  text "Bottom Layer" at 259.277,176.784 h1.52
  text "Copper" at 282.892,176.784 h1.52
  text "1.40mil" at 304.731,176.784 h1.52
  text "6" at 248.865,173.736 h1.52
  text "Bottom Solder" at 259.277,173.736 h1.52
  text "Solder Resist" at 282.892,173.736 h1.52
  text "0.40mil" at 304.731,173.736 h1.52
  text "3.5" at 321.236,173.736 h1.52
  text "7" at 248.865,170.688 h1.52
  text "Bottom Overlay" at 259.277,170.688 h1.52
  text ".Layer_Name" at 14.656,-21.806 h1.52
M13 Component Bodies Top:
  text ".Layer_Name" at 14.656,-21.806 h1.52
M14 Component Bodies Bottom:
  text ".Layer_Name" at 14.656,-21.806 h1.52
M15 Courtyards Top:
  text ".Layer_Name" at 14.656,-21.806 h1.52
M16 Courtyards Bottom:
  text ".Layer_Name" at 14.656,-21.806 h1.52
Drill Drawing:
  lines w0.254: 135.538,77.911 136.944,77.911 136.944,79.316 135.538,79.316 135.538,77.911 ; 135.538,82.478 136.944,82.478 136.241,81.073 135.538,82.478 ; 135.538,84.587 135.89,84.587 136.241,84.235 136.593,84.587 136.944,84.587 136.593,84.938 136.944,85.289 136.593,85.289 136.241,85.641 135.89,85.289 135.538,85.289 135.89,84.938 135.538,84.587
  lines w0.305: 134.264,76.962 216.362,76.962 ; 134.264,86.449 216.362,86.449 ; 142.85,73.8 142.85,89.611 ; 151.287,73.8 151.287,89.611 ; 167.453,73.8 167.453,89.611 ; 174.037,73.8 174.037,89.611 ; 183.568,73.8 183.568,89.611 ; 201.972,73.8 201.972,89.611 ; 134.264,73.8 216.362,73.8 216.362,89.611 134.264,89.611 134.264,73.8
  text "Symbol" at 136.162,87.398 h1.83
  text "Quantity" at 143.799,87.398 h1.83
  text "Finished Hole Size" at 152.235,87.398 h1.83
  text "Plated" at 168.402,87.398 h1.83
  text "Hole Type" at 174.986,87.398 h1.83
  text "Drill Layer Pair" at 184.517,87.398 h1.83
  text "Hole Tolerance" at 202.92,87.398 h1.83
  text "20" at 143.799,84.235 h1.52
  text "11.81mil (0.300mm)" at 152.235,84.235 h1.52
  text "PTH" at 168.402,84.235 h1.52
  text "Round" at 174.986,84.235 h1.52
  text "Top Layer - Bottom Layer" at 184.517,84.235 h1.52
  text "23" at 143.799,81.073 h1.52
  text "19.69mil (0.500mm)" at 152.235,81.073 h1.52
  text "PTH" at 168.402,81.073 h1.52
  text "Round" at 174.986,81.073 h1.52
  text "Top Layer - Bottom Layer" at 184.517,81.073 h1.52
  text "10" at 143.799,77.911 h1.52
  text "40.00mil (1.016mm)" at 152.235,77.911 h1.52
  text "PTH" at 168.402,77.911 h1.52
  text "Round" at 174.986,77.911 h1.52
  text "Top Layer - Bottom Layer" at 184.517,77.911 h1.52
  text "53 Total" at 143.799,74.748 h1.52
  text ".Layer_Name" at 14.656,-21.806 h1.52
M17 Embedded Cavity:
  text ".Layer_Name" at 14.656,-21.806 h1.52
M18 Embedded Assembly:
  text ".Layer_Name" at 14.656,-21.806 h1.52
M19 Embedded Keepout:
  text ".Layer_Name" at 14.656,-21.806 h1.52

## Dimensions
0,-10.16 to 25.4,-10.16 on M2 Board Dimensions
0,0 to 0,27.94 on M2 Board Dimensions
0,0 to 38.1,0 on M2 Board Dimensions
